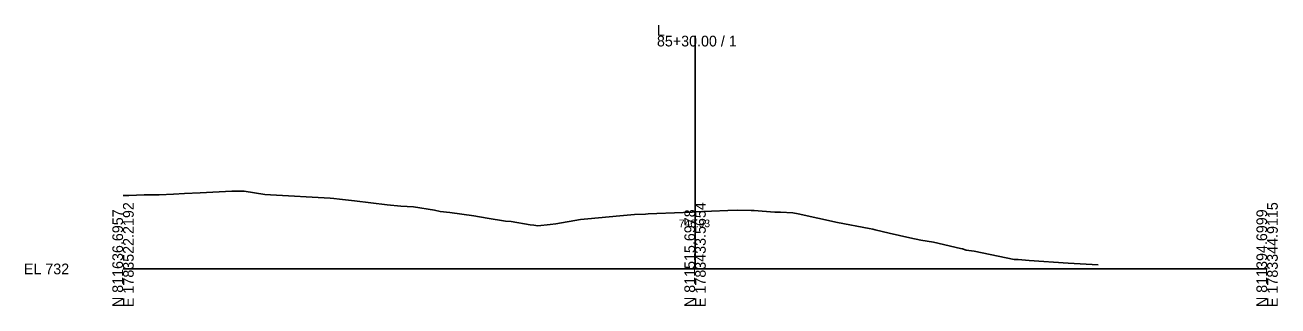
# Model space of a CAD drawing. Extents: x -26 to 7903, y -10 to 9573.
# Drawn here: x 6274.3 to 6602.8, y -9.7 to 63.9 of the extents above; entities that cross this region are included whole.
import ezdxf

# ---------------------------------------------------------------- set-up
doc = ezdxf.new("R2010")
doc.units = 0
for name, color, linetype in [('Exist Cross Section Cell', 7, 'Continuous'), ('Exist XS Center Line Elevation Label', 7, 'Continuous'), ('Exist XS Ground Line', 7, 'Continuous')]:
    doc.layers.add(name, color=color, linetype=linetype)

msp = doc.modelspace()

# ---------------------------------------------------------------- linework, layer by layer
at = {"layer": 'Exist Cross Section Cell'}
for p, q in [((6450, 0), (6450, 61.1)), ((6300, 0), (6450, 0)), ((6450, 0), (6600, 0))]:
    msp.add_line(p, q, dxfattribs=at)
at = {"layer": 'Exist XS Ground Line'}
for p, q in [((6313.2, 19.62), (6316.15, 19.77)), ((6316.15, 19.77), (6320.22, 19.93)), ((6320.22, 19.93), (6328.56, 20.35)), ((6328.56, 20.35), (6331.77, 20.37)), ((6331.77, 20.37), (6337.17, 19.54)), ((6300, 19.21), (6301.49, 19.22)), ((6301.49, 19.22), (6305.52, 19.41)), ((6305.52, 19.41), (6309.5, 19.4)), ((6309.5, 19.4), (6313.2, 19.62)), ((6337.17, 19.54), (6338.68, 19.39)), ((6338.68, 19.39), (6354.33, 18.52)), ((6354.33, 18.52), (6355.3, 18.49)), ((6355.3, 18.49), (6356.74, 18.3)), ((6356.74, 18.3), (6360.71, 17.83)), ((6360.71, 17.83), (6369.28, 16.78)), ((6369.28, 16.78), (6372.85, 16.45)), ((6372.85, 16.45), (6376.2, 16.27)), ((6376.2, 16.27), (6381.69, 15.37)), ((6381.69, 15.37), (6383.14, 15.09)), ((6383.14, 15.09), (6385.67, 14.78)), ((6385.67, 14.78), (6391.95, 13.93)), ((6391.95, 13.93), (6395.47, 13.27)), ((6395.47, 13.27), (6400.33, 12.51)), ((6421.88, 13.13), (6430.29, 13.89)), ((6430.29, 13.89), (6434.13, 14.22)), ((6434.13, 14.22), (6437.04, 14.37)), ((6437.04, 14.37), (6437.71, 14.4)), ((6437.71, 14.4), (6439.99, 14.49)), ((6439.99, 14.49), (6449.26, 14.9)), ((6449.26, 14.9), (6450, 14.93)), ((6450, 14.93), (6458.55, 15.28)), ((6458.55, 15.28), (6461.09, 15.38)), ((6461.09, 15.38), (6464.7, 15.33)), ((6464.7, 15.33), (6465.5, 15.32)), ((6465.5, 15.32), (6467.55, 15.15)), ((6467.55, 15.15), (6470.94, 14.89)), ((6470.94, 14.89), (6472.42, 14.88)), ((6472.42, 14.88), (6475.63, 14.68)), ((6475.63, 14.68), (6477.07, 14.47)), ((6477.07, 14.47), (6487.36, 12.14)), ((6400.33, 12.51), (6401.81, 12.39)), ((6401.81, 12.39), (6406.75, 11.58)), ((6406.75, 11.58), (6407.71, 11.45)), ((6407.71, 11.45), (6408.79, 11.29)), ((6408.79, 11.29), (6412.04, 11.61)), ((6412.04, 11.61), (6413.47, 11.82)), ((6413.47, 11.82), (6419.92, 12.93)), ((6419.92, 12.93), (6421.88, 13.13)), ((6487.36, 12.14), (6495.64, 10.61)), ((6495.64, 10.61), (6496.6, 10.41)), ((6496.6, 10.41), (6497.18, 10.27)), ((6497.18, 10.27), (6500.91, 9.41)), ((6500.91, 9.41), (6506.31, 8.15)), ((6506.31, 8.15), (6509.23, 7.5)), ((6509.23, 7.5), (6512.56, 6.99)), ((6512.56, 6.99), (6519.6, 5.36)), ((6519.6, 5.36), (6520.12, 5.23)), ((6520.12, 5.23), (6521.06, 4.96)), ((6521.06, 4.96), (6523.18, 4.66)), ((6523.18, 4.66), (6533.66, 2.46)), ((6533.66, 2.46), (6534.74, 2.44)), ((6534.74, 2.44), (6537.61, 2.23)), ((6537.61, 2.23), (6547.8, 1.47)), ((6547.8, 1.47), (6555.7, 1.04))]:
    msp.add_line(p, q, dxfattribs=at)

# ---------------------------------------------------------------- texts
at = {"layer": 'Exist Cross Section Cell'}
for s, p in [('L', (6440, 61.1)), ('85+30.00 / 1', (6440, 58.3)), ('EL 732', (6274, -1.4))]:
    msp.add_text(s, height=2.8, dxfattribs=at).set_placement(p)
for s, p in [('E 1783522.2192', (6302.8, -10)), ('E 1783433.5654', (6452.8, -10)), ('E 1783344.9115', (6602.8, -10)), ('N 811636.6957', (6300, -10)), ('N 811515.6978', (6450, -10)), ('N 811394.6999', (6600, -10))]:
    msp.add_text(s, height=2.8, rotation=90, dxfattribs=at).set_placement(p)
at = {"layer": 'Exist XS Center Line Elevation Label'}
msp.add_text('746.93', height=2, dxfattribs=at).set_placement((6445.75, 10.93))

doc.saveas('drawing.dxf')
